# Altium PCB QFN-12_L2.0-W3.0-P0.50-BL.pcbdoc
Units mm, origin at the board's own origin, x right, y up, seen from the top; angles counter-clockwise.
Board outline 16.3 x 15.63 mm, 2 copper layers (Top Layer, Bottom Layer), stack 0 mm thick; 1 components, 0 nets, 12 pads, 0 vias.
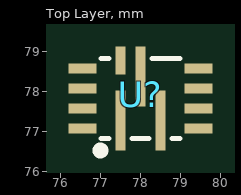
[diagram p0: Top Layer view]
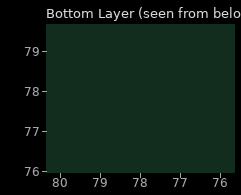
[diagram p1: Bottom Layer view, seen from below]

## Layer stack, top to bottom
Top Layer: signal copper (thickness not stored)
Bottom Layer: signal copper (thickness not stored)

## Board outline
86.15,69.85 69.85,69.85 69.85,85.475 86.15,85.475

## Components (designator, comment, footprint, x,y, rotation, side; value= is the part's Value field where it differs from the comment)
U? "" QFN-12_L2.0-W3.0-P0.50-BL 78,77.925 r0 top

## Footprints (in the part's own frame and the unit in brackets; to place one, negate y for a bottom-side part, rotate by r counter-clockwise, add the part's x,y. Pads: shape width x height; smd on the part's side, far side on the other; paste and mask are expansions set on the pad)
QFN-12_L2.0-W3.0-P0.50-BL [mm]
  rect 0.25x1.5 smd: 1(-0.5,-0.65) 2(0.5,-0.65) 7(0,0.45)
  rect 0.7x0.25 smd: 3(1.45,-0.85) 4(1.45,-0.35) 5(1.45,0.15) 6(1.45,0.65) 9(-1.45,0.65) 10(-1.45,0.15) 11(-1.45,-0.35) 12(-1.45,-0.85)
  rect 0.25x0.7 smd: 8(-0.5,0.85)
  silkscreen extent -1.07,-1.47 0.99,0.9

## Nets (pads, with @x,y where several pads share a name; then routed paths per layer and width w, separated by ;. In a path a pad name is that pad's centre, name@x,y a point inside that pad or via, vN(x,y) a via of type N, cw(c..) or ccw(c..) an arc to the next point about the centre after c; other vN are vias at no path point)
pads on no net: U?.1 U?.2 U?.3 U?.4 U?.5 U?.6 U?.7 U?.8 U?.9 U?.10 U?.11 U?.12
